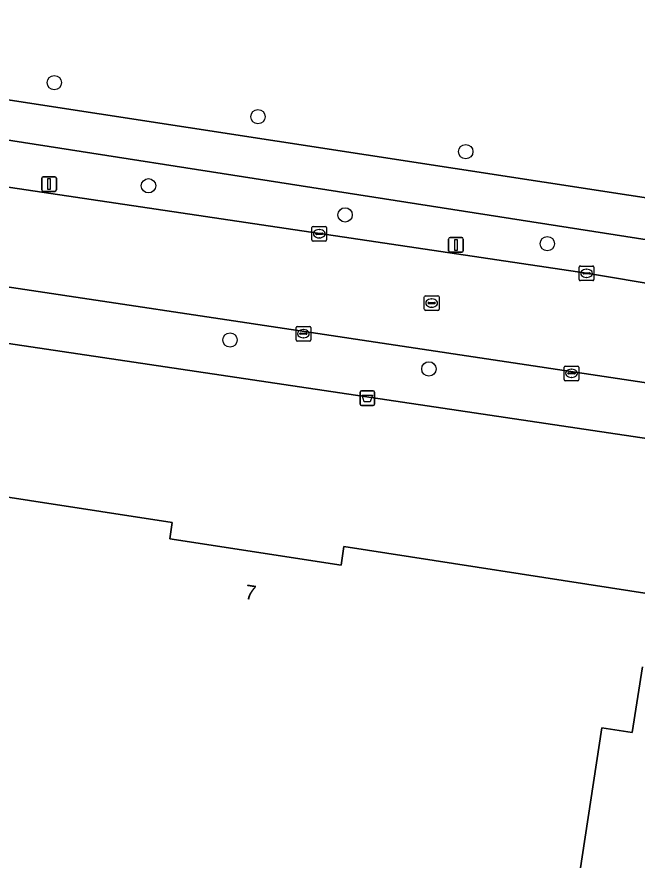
# Model space of a CAD drawing. Extents: x 163008 to 163854, y 382777 to 383982.
# Drawn here: x 163366.1 to 163408.4, y 382959.4 to 383017 of the extents above; entities that cross this region are included whole.
import ezdxf

# ---------------------------------------------------------------- set-up
doc = ezdxf.new("R2010")
doc.units = 0
for name, color, linetype in [('IMGEO_Afvalbak', 7, 'Continuous'), ('IMGEO_Berm_groen', 7, 'Continuous'), ('IMGEO_Boom', 7, 'Continuous'), ('IMGEO_Erf', 7, 'Continuous'), ('IMGEO_Fietspad_gesloten', 7, 'Continuous'), ('IMGEO_Groenvoorziening', 7, 'Continuous'), ('IMGEO_Kolk', 7, 'Continuous'), ('IMGEO_Lichtmast', 7, 'Continuous'), ('IMGEO_Pand', 7, 'Continuous'), ('IMGEO_Pand_nummerreeks', 7, 'Continuous'), ('IMGEO_Rijbaan_lokaal_gesloten', 7, 'Continuous'), ('IMGEO_Rioolput', 7, 'Continuous'), ('IMGEO_Voetpad_open', 7, 'Continuous')]:
    doc.layers.add(name, color=color, linetype=linetype)

msp = doc.modelspace()

# ---------------------------------------------------------------- linework, layer by layer
at = {"layer": 'IMGEO_Afvalbak'}
for p, q in [((163389.537, 382990.565), (163389.537, 382991.365)), ((163389.537, 382991.365), (163389.537, 382990.565)), ((163389.637, 382991.465), (163390.427, 382991.465)), ((163390.427, 382991.465), (163389.637, 382991.465)), ((163390.527, 382991.365), (163390.527, 382990.565)), ((163390.527, 382990.565), (163390.527, 382991.365)), ((163390.427, 382990.465), (163389.637, 382990.465)), ((163389.637, 382990.465), (163390.427, 382990.465))]:
    msp.add_line(p, q, dxfattribs=at)
msp.add_lwpolyline([(163389.68, 382991.179), (163390.384, 382991.179), (163390.235, 382990.709), (163389.829, 382990.709), (163389.68, 382991.179)], dxfattribs=at)
for centre, start, end in [((163389.637, 382991.365), 90, 180), ((163389.637, 382991.365), 90, 180), ((163390.427, 382991.365), 0, 90), ((163390.427, 382991.365), 360, 90), ((163389.637, 382990.565), 180, 270), ((163389.637, 382990.565), 180, 270), ((163390.427, 382990.565), 270, 0), ((163390.427, 382990.565), 270, 0)]:
    msp.add_arc(centre, 0.1, start, end, dxfattribs=at)
at = {"layer": 'IMGEO_Berm_groen'}
for points in [[(163339.774, 383012.591), (163332.089, 383015.205), (163331.816, 383013.6), (163333.197, 383011.915), (163336.571, 383011.409), (163336.344, 383009.715), (163404.987, 382999.481), (163410.269, 382998.605)], [(163411.354, 382999.501), (163411.369, 383000.271), (163410.874, 383001.497), (163339.774, 383012.591)]]:
    msp.add_lwpolyline(points, dxfattribs=at)
at = {"layer": 'IMGEO_Boom'}
for centre in [(163368.689, 383012.49), (163382.577, 383010.17), (163396.744, 383007.785), (163375.112, 383005.454), (163388.519, 383003.468), (163402.307, 383001.504), (163380.672, 382994.933), (163394.232, 382992.958)]:
    msp.add_circle(centre, 0.489, dxfattribs=at)
at = {"layer": 'IMGEO_Erf'}
for points in [[(163411.357, 382987.861), (163338.968, 382998.653), (163334.397, 382999.382), (163329.139, 383000.29), (163329, 383000.314), (163328.682, 383000.362), (163320.711, 382929.78), (163328.183, 382928.813), (163326.434, 382916.263)], [(163363.572, 382923.804), (163338.52, 382927.67), (163333.578, 382928.433), (163337.312, 382952.627), (163346.874, 382951.151), (163346.924, 382951.476), (163366.603, 382948.648), (163367.524, 382954.619), (163339.041, 382959.015), (163334.099, 382959.778), (163335.673, 382969.98), (163330.09, 382970.842), (163332.93, 382989.239), (163376.732, 382982.479), (163376.562, 382981.375), (163388.243, 382979.572), (163388.438, 382980.834), (163409.558, 382977.575)], [(163408.795, 382972.634), (163408.102, 382968.143), (163406.034, 382968.462), (163404.515, 382958.616), (163406.662, 382958.285), (163405.206, 382948.848), (163384.455, 382952.05), (163383.989, 382949.026), (163379.105, 382949.78), (163379.71, 382953.7), (163377.097, 382954.103), (163376.489, 382950.166), (163371.506, 382950.935), (163371.541, 382951.165), (163369.758, 382951.44), (163369.27, 382948.278), (163394.85, 382944.331), (163393.848, 382937.839), (163396.869, 382937.373), (163403.403, 382936.364), (163402.396, 382929.842), (163420.669, 382927.024)]]:
    msp.add_lwpolyline(points, dxfattribs=at)
at = {"layer": 'IMGEO_Fietspad_gesloten'}
for points in [[(163617.09, 382973.246), (163586.506, 382977.714), (163544.618, 382984.04), (163541.477, 382984.514), (163486.6, 382992.801), (163428.914, 383001.629), (163426.083, 383002.018), (163341.665, 383014.986), (163340.004, 383015.426), (163335.408, 383017.05), (163332.11, 383018.101), (163328.736, 383018.876), (163327.116, 383019.173), (163322.281, 383020.078), (163261.942, 383031.619), (163259.432, 383032.112), (163254.513, 383033.076), (163252.6, 383033.489), (163238.283, 383036.725), (163237.872, 383034.497), (163244.23, 383033.069)], [(163242.69, 383030.464), (163245.735, 383028.612), (163245.633, 383029.321), (163245.893, 383029.972), (163246.486, 383030.601), (163247.057, 383030.984), (163247.859, 383031.273), (163248.857, 383031.23), (163251.557, 383030.68), (163254, 383030.182), (163259.018, 383029.356), (163326.513, 383016.383), (163327.352, 383016.222), (163332.089, 383015.205), (163339.774, 383012.591), (163410.874, 383001.497), (163411.369, 383000.271), (163411.354, 382999.501)]]:
    msp.add_lwpolyline(points, dxfattribs=at)
at = {"layer": 'IMGEO_Groenvoorziening'}
msp.add_lwpolyline([(163427.394, 383024.502), (163413.969, 383052.216), (163399.398, 383044.736), (163398.169, 383047.501), (163397.08, 383046.99), (163396.945, 383047.255), (163374.565, 383036.515), (163340.762, 383020.485), (163340.731, 383020.283), (163341.742, 383020.136), (163341.505, 383018.514), (163340.474, 383018.665), (163340.004, 383015.426), (163341.665, 383014.986), (163426.083, 383002.018), (163426.994, 383007.752), (163428.656, 383020.356), (163428.623, 383021.086)], dxfattribs=at)
at = {"layer": 'IMGEO_Kolk'}
for p, q in [((163386.259, 383001.757), (163386.259, 383002.609)), ((163386.334, 383002.683), (163387.186, 383002.683)), ((163387.26, 383002.609), (163387.26, 383001.757)), ((163386.518, 383002.177), (163386.518, 383002.189)), ((163386.956, 383002.14), (163386.558, 383002.14)), ((163386.561, 383002.226), (163386.959, 383002.226)), ((163386.747, 383002.463), (163386.772, 383002.463)), ((163387.002, 383002.189), (163387.002, 383002.177)), ((163387.186, 383001.683), (163386.334, 383001.683)), ((163386.77, 383001.903), (163386.745, 383001.903)), ((163404.486, 382999.055), (163404.486, 382999.907)), ((163404.561, 382999.981), (163405.413, 382999.981)), ((163404.974, 382999.761), (163404.999, 382999.761)), ((163405.487, 382999.907), (163405.487, 382999.055)), ((163404.745, 382999.475), (163404.745, 382999.487)), ((163405.183, 382999.438), (163404.785, 382999.438)), ((163404.788, 382999.524), (163405.186, 382999.524)), ((163404.997, 382999.201), (163404.972, 382999.201)), ((163405.229, 382999.487), (163405.229, 382999.475)), ((163405.413, 382998.981), (163404.561, 382998.981)), ((163385.175, 382994.936), (163385.175, 382995.788)), ((163385.25, 382995.862), (163386.102, 382995.862)), ((163386.176, 382995.788), (163386.176, 382994.936)), ((163385.434, 382995.356), (163385.434, 382995.368)), ((163385.872, 382995.319), (163385.474, 382995.319)), ((163385.477, 382995.405), (163385.875, 382995.405)), ((163385.663, 382995.642), (163385.688, 382995.642)), ((163385.918, 382995.368), (163385.918, 382995.356)), ((163386.102, 382994.862), (163385.25, 382994.862)), ((163385.686, 382995.082), (163385.661, 382995.082)), ((163403.457, 382992.231), (163403.457, 382993.083)), ((163403.532, 382993.157), (163404.384, 382993.157)), ((163403.945, 382992.937), (163403.97, 382992.937)), ((163404.458, 382993.083), (163404.458, 382992.231)), ((163403.716, 382992.651), (163403.716, 382992.663)), ((163404.154, 382992.614), (163403.756, 382992.614)), ((163403.759, 382992.7), (163404.157, 382992.7)), ((163403.968, 382992.377), (163403.943, 382992.377)), ((163404.2, 382992.663), (163404.2, 382992.651)), ((163404.384, 382992.157), (163403.532, 382992.157))]:
    msp.add_line(p, q, dxfattribs=at)
for points in [[(163386.259, 383001.757), (163386.259, 383002.609)], [(163386.334, 383002.683), (163387.186, 383002.683)], [(163387.26, 383002.609), (163387.26, 383001.757)], [(163387.186, 383001.683), (163386.334, 383001.683)], [(163404.486, 382999.055), (163404.486, 382999.907)], [(163404.561, 382999.981), (163405.413, 382999.981)], [(163405.487, 382999.907), (163405.487, 382999.055)], [(163405.413, 382998.981), (163404.561, 382998.981)], [(163385.175, 382994.936), (163385.175, 382995.788)], [(163385.25, 382995.862), (163386.102, 382995.862)], [(163386.176, 382995.788), (163386.176, 382994.936)], [(163386.102, 382994.862), (163385.25, 382994.862)], [(163403.457, 382992.231), (163403.457, 382993.083)], [(163403.532, 382993.157), (163404.384, 382993.157)], [(163404.458, 382993.083), (163404.458, 382992.231)], [(163404.384, 382992.157), (163403.532, 382992.157)]]:
    msp.add_lwpolyline(points, dxfattribs=at)
for centre, radius, start, end in [((163386.336, 383002.607), 0.0765, 91.55205, 178.44795), ((163386.336, 383002.607), 0.0765, 91.55205, 178.44795), ((163387.184, 383002.607), 0.0765, 1.55205, 88.44795), ((163387.184, 383002.607), 0.0765, 1.55205, 88.44795), ((163386.558, 383002.186), 0.0403, 85.87752, 175.75265), ((163386.555, 383002.176), 0.0366, 178.93798, 274.71019), ((163386.959, 383002.183), 0.043, 264.86636, 352.45326), ((163386.963, 383002.188), 0.0386, 1.73085, 96.63898), ((163386.336, 383001.759), 0.0765, 181.55205, 268.44795), ((163386.336, 383001.759), 0.0765, 181.55205, 268.44795), ((163387.184, 383001.759), 0.0765, 271.55205, 358.44795), ((163387.184, 383001.759), 0.0765, 271.55205, 358.44795), ((163404.563, 382999.905), 0.0765, 91.55205, 178.44795), ((163404.563, 382999.905), 0.0765, 91.55205, 178.44795), ((163405.411, 382999.905), 0.0765, 1.55205, 88.44795), ((163405.411, 382999.905), 0.0765, 1.55205, 88.44795), ((163404.785, 382999.484), 0.0403, 85.87752, 175.75265), ((163404.782, 382999.474), 0.0366, 178.93798, 274.71019), ((163405.186, 382999.481), 0.043, 264.86636, 352.45326), ((163405.19, 382999.486), 0.0386, 1.73085, 96.63898), ((163404.563, 382999.057), 0.0765, 181.55205, 268.44795), ((163404.563, 382999.057), 0.0765, 181.55205, 268.44795), ((163405.411, 382999.057), 0.0765, 271.55205, 358.44795), ((163405.411, 382999.057), 0.0765, 271.55205, 358.44795), ((163385.252, 382995.786), 0.0765, 91.55205, 178.44795), ((163385.252, 382995.786), 0.0765, 91.55205, 178.44795), ((163386.1, 382995.786), 0.0765, 1.55205, 88.44795), ((163386.1, 382995.786), 0.0765, 1.55205, 88.44795), ((163385.474, 382995.365), 0.0403, 85.87752, 175.75265), ((163385.471, 382995.355), 0.0366, 178.93798, 274.71019), ((163385.875, 382995.362), 0.043, 264.86636, 352.45326), ((163385.879, 382995.367), 0.0386, 1.73085, 96.63898), ((163385.252, 382994.938), 0.0765, 181.55205, 268.44795), ((163385.252, 382994.938), 0.0765, 181.55205, 268.44795), ((163386.1, 382994.938), 0.0765, 271.55205, 358.44795), ((163386.1, 382994.938), 0.0765, 271.55205, 358.44795), ((163403.534, 382993.081), 0.0765, 91.55205, 178.44795), ((163403.534, 382993.081), 0.0765, 91.55205, 178.44795), ((163404.382, 382993.081), 0.0765, 1.55205, 88.44795), ((163404.382, 382993.081), 0.0765, 1.55205, 88.44795), ((163403.756, 382992.66), 0.0403, 85.87752, 175.75265), ((163403.753, 382992.65), 0.0366, 178.93798, 274.71019), ((163404.157, 382992.657), 0.043, 264.86636, 352.45326), ((163404.161, 382992.662), 0.0386, 1.73085, 96.63898), ((163403.534, 382992.233), 0.0765, 181.55205, 268.44795), ((163403.534, 382992.233), 0.0765, 181.55205, 268.44795), ((163404.382, 382992.233), 0.0765, 271.55205, 358.44795), ((163404.382, 382992.233), 0.0765, 271.55205, 358.44795)]:
    msp.add_arc(centre, radius, start, end, dxfattribs=at)
for centre, major_axis, ratio, start_param, end_param in [((163386.746, 383002.183), (-0.387, 0.002), 0.722429, 4.712389, 7.853982), ((163386.771, 383002.183), (-0.39, 0.002), 0.717154, 1.570796, 4.712389), ((163404.973, 382999.481), (-0.387, 0.002), 0.722429, 4.712389, 7.853982), ((163404.998, 382999.481), (-0.39, 0.002), 0.717154, 1.570796, 4.712389), ((163385.662, 382995.362), (-0.387, 0.002), 0.722429, 4.712389, 7.853982), ((163385.687, 382995.362), (-0.39, 0.002), 0.717154, 1.570796, 4.712389), ((163403.944, 382992.657), (-0.387, 0.002), 0.722429, 4.712389, 7.853982), ((163403.969, 382992.657), (-0.39, 0.002), 0.717154, 1.570796, 4.712389)]:
    msp.add_ellipse(centre, major_axis=major_axis, ratio=ratio, start_param=start_param, end_param=end_param, dxfattribs=at)
at = {"layer": 'IMGEO_Lichtmast'}
for p, q in [((163367.938, 383006.075), (163368.728, 383006.075)), ((163368.728, 383006.075), (163367.938, 383006.075)), ((163367.838, 383005.175), (163367.838, 383005.975)), ((163367.838, 383005.975), (163367.838, 383005.175)), ((163368.828, 383005.975), (163368.828, 383005.175)), ((163368.828, 383005.175), (163368.828, 383005.975)), ((163368.728, 383005.075), (163367.938, 383005.075)), ((163367.938, 383005.075), (163368.728, 383005.075)), ((163395.58, 383001.022), (163395.58, 383001.822)), ((163395.58, 383001.822), (163395.58, 383001.022)), ((163395.68, 383001.922), (163396.47, 383001.922)), ((163396.47, 383001.922), (163395.68, 383001.922)), ((163396.57, 383001.822), (163396.57, 383001.022)), ((163396.57, 383001.022), (163396.57, 383001.822)), ((163396.47, 383000.922), (163395.68, 383000.922)), ((163395.68, 383000.922), (163396.47, 383000.922))]:
    msp.add_line(p, q, dxfattribs=at)
for points in [[(163368.258, 383005.95), (163368.408, 383005.95), (163368.408, 383005.2), (163368.258, 383005.2), (163368.258, 383005.95)], [(163396, 383001.797), (163396.15, 383001.797), (163396.15, 383001.047), (163396, 383001.047), (163396, 383001.797)]]:
    msp.add_lwpolyline(points, dxfattribs=at)
for centre, start, end in [((163367.938, 383005.975), 90, 180), ((163367.938, 383005.975), 90, 180), ((163368.728, 383005.975), 0, 90), ((163368.728, 383005.975), 360, 90), ((163367.938, 383005.175), 180, 270), ((163367.938, 383005.175), 180, 270), ((163368.728, 383005.175), 270, 0), ((163368.728, 383005.175), 270, 0), ((163395.68, 383001.822), 90, 180), ((163395.68, 383001.822), 90, 180), ((163396.47, 383001.822), 0, 90), ((163396.47, 383001.822), 360, 90), ((163395.68, 383001.022), 180, 270), ((163395.68, 383001.022), 180, 270), ((163396.47, 383001.022), 270, 0), ((163396.47, 383001.022), 270, 0)]:
    msp.add_arc(centre, 0.1, start, end, dxfattribs=at)
at = {"layer": 'IMGEO_Pand'}
for points in [[(163409.558, 382977.575), (163388.438, 382980.834), (163388.243, 382979.572), (163376.562, 382981.375), (163376.732, 382982.479), (163332.93, 382989.239), (163330.09, 382970.842), (163335.673, 382969.98), (163334.099, 382959.778), (163339.041, 382959.015), (163367.524, 382954.619), (163366.603, 382948.648), (163346.924, 382951.476), (163346.874, 382951.151), (163337.312, 382952.627), (163333.578, 382928.433), (163338.52, 382927.67), (163363.572, 382923.804), (163395.181, 382919.138), (163418.814, 382915.446)], [(163420.669, 382927.024), (163402.396, 382929.842), (163403.403, 382936.364), (163396.869, 382937.373), (163393.848, 382937.839), (163394.85, 382944.331), (163369.27, 382948.278), (163369.758, 382951.44), (163371.541, 382951.165), (163371.506, 382950.935), (163376.489, 382950.166), (163377.097, 382954.103), (163379.71, 382953.7), (163379.105, 382949.78), (163383.989, 382949.026), (163384.455, 382952.05), (163405.206, 382948.848), (163406.662, 382958.285), (163404.515, 382958.616), (163406.034, 382968.462), (163408.102, 382968.143), (163408.795, 382972.634)]]:
    msp.add_lwpolyline(points, dxfattribs=at)
at = {"layer": 'IMGEO_Rijbaan_lokaal_gesloten'}
for points in [[(163292.545, 383009.569), (163296.84, 383008.817), (163304.96, 383007.61), (163321.045, 383005.203), (163329.509, 383003.951), (163334.952, 383003.075), (163339.568, 383002.444), (163411.931, 382991.584), (163416.286, 382990.97), (163423.758, 382989.792), (163438.655, 382987.556), (163481.173, 382981.103), (163506.122, 382977.311), (163550.446, 382970.596), (163562.809, 382968.717), (163570.543, 382967.542), (163594.132, 382963.957), (163599.415, 382963.154), (163615.953, 382960.64), (163617.8, 382960.359)], [(163620.509, 382966.927), (163617.533, 382967.225), (163535.444, 382979.722), (163530.764, 382980.419), (163493.409, 382986.066), (163488.831, 382986.752), (163415.02, 382997.894), (163410.269, 382998.605), (163404.987, 382999.481), (163336.344, 383009.715)]]:
    msp.add_lwpolyline(points, dxfattribs=at)
at = {"layer": 'IMGEO_Rioolput'}
for p, q in [((163393.921, 382997.027), (163393.921, 382997.879)), ((163393.996, 382997.953), (163394.848, 382997.953)), ((163394.18, 382997.447), (163394.18, 382997.459)), ((163394.618, 382997.41), (163394.22, 382997.41)), ((163394.223, 382997.496), (163394.621, 382997.496)), ((163394.409, 382997.733), (163394.434, 382997.733)), ((163394.664, 382997.459), (163394.664, 382997.447)), ((163394.922, 382997.879), (163394.922, 382997.027)), ((163394.848, 382996.953), (163393.996, 382996.953)), ((163394.432, 382997.173), (163394.407, 382997.173))]:
    msp.add_line(p, q, dxfattribs=at)
for points in [[(163393.921, 382997.027), (163393.921, 382997.879)], [(163393.996, 382997.953), (163394.848, 382997.953)], [(163394.922, 382997.879), (163394.922, 382997.027)], [(163394.848, 382996.953), (163393.996, 382996.953)]]:
    msp.add_lwpolyline(points, dxfattribs=at)
for centre, radius, start, end in [((163393.998, 382997.877), 0.0765, 91.55205, 178.44795), ((163393.998, 382997.877), 0.0765, 91.55205, 178.44795), ((163394.22, 382997.456), 0.0403, 85.87752, 175.75265), ((163394.217, 382997.446), 0.0366, 178.93798, 274.71019), ((163394.621, 382997.453), 0.043, 264.86636, 352.45326), ((163394.625, 382997.458), 0.0386, 1.73085, 96.63898), ((163394.846, 382997.877), 0.0765, 1.55205, 88.44795), ((163394.846, 382997.877), 0.0765, 1.55205, 88.44795), ((163393.998, 382997.029), 0.0765, 181.55205, 268.44795), ((163393.998, 382997.029), 0.0765, 181.55205, 268.44795), ((163394.846, 382997.029), 0.0765, 271.55205, 358.44795), ((163394.846, 382997.029), 0.0765, 271.55205, 358.44795)]:
    msp.add_arc(centre, radius, start, end, dxfattribs=at)
for centre, major_axis, ratio, start_param, end_param in [((163394.408, 382997.453), (-0.387, 0.002), 0.722429, 4.712389, 7.853982), ((163394.433, 382997.453), (-0.39, 0.002), 0.717154, 1.570796, 4.712389)]:
    msp.add_ellipse(centre, major_axis=major_axis, ratio=ratio, start_param=start_param, end_param=end_param, dxfattribs=at)
at = {"layer": 'IMGEO_Voetpad_open'}
msp.add_lwpolyline([(163411.357, 382987.861), (163411.931, 382991.584), (163339.568, 383002.444), (163338.968, 382998.653)], close=True, dxfattribs=at)

# ---------------------------------------------------------------- texts
at = {"layer": 'IMGEO_Pand_nummerreeks'}
msp.add_text('7', height=1, rotation=351.22802, dxfattribs=at).set_placement((163381.629, 382977.273))

doc.saveas('drawing.dxf')
